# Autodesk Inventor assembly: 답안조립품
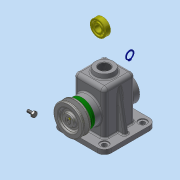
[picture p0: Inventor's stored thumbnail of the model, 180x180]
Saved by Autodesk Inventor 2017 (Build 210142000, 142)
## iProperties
Part Number: 답안조립품
Material: 일반
Document SubType Name: Assembly
Designer: MRC
Author: MRC
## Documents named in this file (10)
- C:\Users\MRC\Desktop\700907V1010\답안조립품.iam
- C:\Users\MRC\Desktop\700907V1010\본체.ipt
- C:\Users\MRC\Desktop\700907V1010\축.ipt
- C:\Users\MRC\Desktop\700907V1010\V-벨트풀리.ipt
- C:\Users\MRC\Desktop\700907V1010\키 5 x 5 x 14.ipt
- C:\Users\MRC\Desktop\700907V1010\베어링 15 x 35 x 11.ipt
- C:\Users\MRC\Desktop\700907V1010\멈춤링 15 x 1.ipt
- C:\Users\MRC\Desktop\700907V1010\앞커버.ipt
- C:\Users\MRC\Desktop\700907V1010\볼트 M4 x 10.ipt
- C:\Users\MRC\Desktop\700907V1010\볼트 M6 x 12.ipt
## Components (1 placed, 1 different names)
1. V-벨트풀리:1
